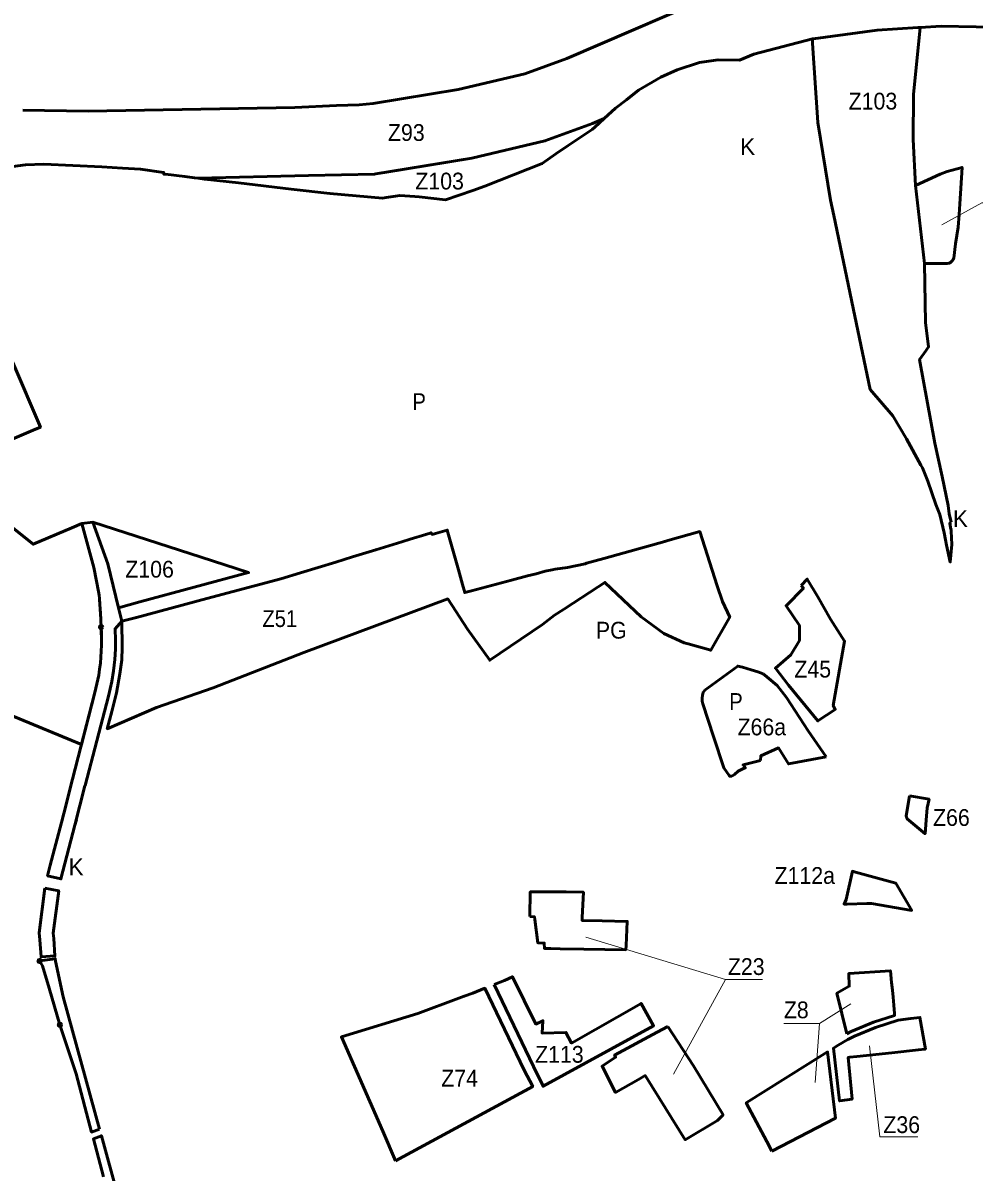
# Model space of a CAD drawing. Extents: x -650246 to -642674, y -1074280 to -1066767.
# Drawn here: x -649169 to -647810, y -1070690 to -1069047 of the extents above; entities that cross this region are included whole.
import ezdxf

# ---------------------------------------------------------------- set-up
doc = ezdxf.new("R2010")
doc.units = 0
doc.header["$LTSCALE"] = 9.6
doc.header["$PDMODE"] = 32
doc.header["$PDSIZE"] = 4.8
for name, color, linetype, lineweight in [('44', 7, 'Continuous', 53), ('45', 7, 'Continuous', 53), ('46', 7, 'Continuous', 13), ('48', 7, 'Continuous', 13), ('60', 7, 'Continuous', 35)]:
    doc.layers.add(name, color=color, linetype=linetype, lineweight=lineweight)

msp = doc.modelspace()

# ---------------------------------------------------------------- linework, layer by layer
at = {"layer": '44'}
for p, q in [((-649058.858, -1069889.759), (-649057.868, -1069910.51)), ((-649057.134, -1069932.873), (-649057.868, -1069910.51)), ((-649146.163, -1070347.543), (-649145.424, -1070357.637))]:
    msp.add_line(p, q, dxfattribs=at)
for points in [[(-648156.739, -1068996.273), (-648392.002, -1069097.554), (-648451.865, -1069119.456), (-648547.243, -1069141.81), (-648668.959, -1069161.838), (-648688.912, -1069163.603), (-648721.315, -1069164.952), (-648781.015, -1069167.44), (-649076.02, -1069172.683), (-649169.781, -1069171.432)], [(-648040.456, -1069069.483), (-648039.666, -1069069.279), (-647948.18, -1069057.276)], [(-647948.18, -1069057.276), (-648039.666, -1069069.279), (-648040.456, -1069069.483)], [(-647948.18, -1069057.276), (-647889.927, -1069053.218), (-647886.615, -1069053.052)], [(-647886.615, -1069053.052), (-647889.927, -1069053.218), (-647948.18, -1069057.276)], [(-647887.087, -1069527.229), (-647878.73, -1069515.45), (-647874.75, -1069509.84), (-647878.93, -1069475.09), (-647880.326, -1069390.832), (-647893.553, -1069279.021), (-647896.67, -1069213.573), (-647896.362, -1069149.171), (-647886.615, -1069053.052)], [(-647886.615, -1069053.052), (-647856.541, -1069051.548), (-647756.441, -1069053.207), (-647708.401, -1069056.275), (-647511.94, -1069076.703), (-647426.417, -1069084.624), (-647344.902, -1069091.02), (-647270.522, -1069094.255), (-647197.498, -1069094.255), (-647123.648, -1069091.043), (-647065.688, -1069087.73)], [(-648665.007, -1069262.694), (-648527.693, -1069239.938), (-648423.173, -1069215.44), (-648354.978, -1069190.492), (-648338.523, -1069183.389), (-648322.14, -1069168.56), (-648306.83, -1069156.57), (-648289.25, -1069142.79), (-648257.5, -1069124.41), (-648234.22, -1069113.6), (-648202.46, -1069103.3), (-648175.65, -1069099.64), (-648144.866, -1069099.987), (-648124.327, -1069091.181), (-648040.705, -1069069.547), (-648040.456, -1069069.483)], [(-648040.456, -1069069.483), (-648040.537, -1069075.531), (-648036.291, -1069139.458), (-648034.421, -1069167.61)], [(-648034.421, -1069167.61), (-648033, -1069189), (-648015, -1069300), (-648010.092, -1069322.087), (-647980.331, -1069465.915), (-647958.34, -1069570.699), (-647925.99, -1069608.57)], [(-648354.978, -1069190.492), (-648423.173, -1069215.44), (-648527.693, -1069239.938), (-648652.716, -1069260.657)], [(-648526.15, -1069286.21), (-648508.95, -1069280.01), (-648427.08, -1069247.75), (-648407.73, -1069233.88), (-648389.91, -1069221.86), (-648355.81, -1069198.88), (-648351.77, -1069195.88), (-648338.523, -1069183.389), (-648354.978, -1069190.492)], [(-649202.63, -1069254.4), (-649165.62, -1069249.43), (-649139.63, -1069248.73), (-649056.95, -1069252.55), (-649026.955, -1069254.366), (-649001.3, -1069255.92), (-648968.49, -1069260.36), (-648968.05, -1069263.06), (-648965.8, -1069262.75), (-648937.91, -1069266.51), (-648924.13, -1069268.21), (-648918.889, -1069268.875)], [(-648918.889, -1069268.875), (-648761.189, -1069265.035), (-648666.827, -1069262.738), (-648665.007, -1069262.694)], [(-648666.827, -1069262.738), (-648761.189, -1069265.035), (-648918.889, -1069268.875), (-648909.86, -1069270.02), (-648861.49, -1069275.34), (-648785.92, -1069284.2), (-648730.66, -1069290.43), (-648730.66, -1069290.43), (-648655.53, -1069297.18), (-648650.06, -1069296.39), (-648636.85, -1069294.49)], [(-648652.716, -1069260.657), (-648665.007, -1069262.694), (-648666.827, -1069262.738)], [(-648636.85, -1069294.49), (-648630.82, -1069293.63), (-648609.425, -1069295.033), (-648603.228, -1069295.53), (-648565.18, -1069299.46), (-648526.15, -1069286.21)], [(-647865.69, -1069647.32), (-647887.649, -1069528.021), (-647887.087, -1069527.229)], [(-647925.99, -1069608.57), (-647906.16, -1069641.48), (-647885.665, -1069678.788), (-647885.663, -1069678.794), (-647883.51, -1069682.71), (-647875.82, -1069701.85)], [(-647842.438, -1069760.647), (-647845.086, -1069748.753), (-647846.484, -1069736.663), (-647855.158, -1069695.232), (-647865.69, -1069647.32)], [(-647875.82, -1069701.85), (-647864.19, -1069735.12), (-647858.44, -1069749.43), (-647852.63, -1069775.7), (-647850.66, -1069785.74), (-647849.165, -1069793.367), (-647843.74, -1069817.63), (-647841.402, -1069792.351)], [(-649061.138, -1069979.243), (-649061.138, -1069979.243), (-649061.139, -1069979.254), (-649066.487, -1070004.267), (-649098.65, -1070127.795), (-649110.925, -1070177.113), (-649114.174, -1070189.816), (-649130.712, -1070250.935), (-649134.294, -1070266.095), (-649115.159, -1070270.568), (-649095.152, -1070193.731), (-649093.095, -1070186.132), (-649095.152, -1070193.731), (-649080.924, -1070137.409), (-649080.38, -1070136.996), (-649047.131, -1070009.304), (-649042.468, -1069988.477), (-649042.468, -1069988.477), (-649039.966, -1069973.035), (-649037.98, -1069956.626), (-649037.322, -1069942.129), (-649037.137, -1069928.996), (-649037.665, -1069912.977), (-649028.017, -1069902.109), (-649032.928, -1069882.782), (-649048, -1069820), (-649069.4, -1069760.67), (-649085.41, -1069762.44), (-649068, -1069825.147), (-649060.897, -1069861.994)], [(-647841.402, -1069792.351), (-647842.489, -1069773.282), (-647842.622, -1069770.956), (-647843.337, -1069769.013), (-647843.443, -1069768.293), (-647843.458, -1069768.256), (-647843.449, -1069768.252), (-647844.371, -1069761.991), (-647842.438, -1069760.647)], [(-649138.43, -1070283.6), (-649146.163, -1070347.543), (-649146.163, -1070347.543)], [(-649125.503, -1070355.837), (-649126.069, -1070348.097), (-649118.257, -1070287.455), (-649138.43, -1070283.6)], [(-649145.424, -1070357.637), (-649143.633, -1070382.123), (-649123.693, -1070380.572), (-649125.503, -1070355.837)], [(-649059.951, -1070628.223), (-649112.14, -1070439.152), (-649123.138, -1070388.16), (-649123.385, -1070384.775), (-649145.73, -1070387.91)], [(-649145.73, -1070387.91), (-649141.48, -1070394.84), (-649132.07, -1070426.81), (-649116.56, -1070479.19)], [(-649116.56, -1070479.19), (-649093.2, -1070549.1), (-649071.33, -1070632.6), (-649059.951, -1070628.223)], [(-649025.129, -1070754.377), (-649047.11, -1070674.743), (-649050.081, -1070663.981), (-649057.338, -1070637.689), (-649068.65, -1070642.23), (-649068.65, -1070642.23), (-649054.31, -1070696.44)]]:
    msp.add_lwpolyline(points, dxfattribs=at)
msp.add_lwpolyline([(-647860.52, -1069390.72), (-647848.24, -1069390.65), (-647845.25, -1069390.07), (-647843.41, -1069389.23), (-647841.81, -1069387.99), (-647840.42, -1069386.51), (-647839.4, -1069384.73), (-647838.79, -1069382.86), (-647836.2, -1069362.68), (-647832.29, -1069338.58), (-647832.29, -1069338.58), (-647831.19, -1069320.69), (-647830.23, -1069305.38), (-647826.928, -1069253.199), (-647848.17, -1069259.21), (-647858.37, -1069263.03), (-647893.553, -1069279.017), (-647880.326, -1069390.832)], close=True, dxfattribs=at)
at = {"layer": '44', "lineweight": 13}
msp.add_lwpolyline([(-647751.811, -1069303.761), (-647798.61, -1069303.761), (-647856.005, -1069335.572)], dxfattribs=at)
msp.add_lwpolyline([(-647751.811, -1069303.761), (-647798.61, -1069303.761), (-647856.005, -1069335.572)], dxfattribs=at)
at = {"layer": '44'}
for centre, radius, start, end in [((-648354.978, -1069190.492), 0.000000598, 264.13978, 298.69712), ((-649633.43, -1069918.001), 575.266, 2.81398, 5.58706), ((-649347.129, -1069931.193), 290, 350.46253, 4.08974), ((-649347.129, -1069931.193), 290, 359.66809, 4.08974)]:
    msp.add_arc(centre, radius, start, end, dxfattribs=at)
for p in [(-649145.73, -1070387.91), (-649116.56, -1070479.19)]:
    msp.add_point(p, dxfattribs=at)
at = {"layer": '45'}
for p, q in [((-649032.928, -1069882.782), (-649002.558, -1069874.585)), ((-649032.928, -1069882.782), (-649002.558, -1069874.585)), ((-649057.868, -1069910.51), (-649058.82, -1069890.548))]:
    msp.add_line(p, q, dxfattribs=at)
for points in [[(-649241.11, -1069665.9), (-649155.082, -1069629.097), (-649144.57, -1069624.6), (-649184.1, -1069532.2)], [(-649060.897, -1069861.994), (-649068, -1069825.147), (-649085.41, -1069762.44), (-649085.41, -1069762.44), (-649099.75, -1069768.575), (-649154.76, -1069792.11), (-649184.05, -1069768.45)], [(-649002.558, -1069874.585), (-648846.924, -1069832.58), (-648914.48, -1069810.75), (-649069.4, -1069760.67)], [(-649069.4, -1069760.67), (-649048, -1069820), (-649032.928, -1069882.782)], [(-649002.558, -1069874.585), (-648846.924, -1069832.58), (-648914.48, -1069810.75), (-649069.4, -1069760.67)], [(-649069.4, -1069760.67), (-649048, -1069820), (-649032.928, -1069882.782)], [(-649202.375, -1070030.469), (-649085.737, -1070078.201), (-649066.487, -1070004.267), (-649061.139, -1069979.254), (-649061.138, -1069979.243), (-649061.138, -1069979.243)], [(-648128.48, -1069971.7), (-648140.96, -1069968.01), (-648147.46, -1069966.19), (-648194.84, -1070000.49)], [(-648111.44, -1069977.32), (-648118.75, -1069974.53), (-648128.48, -1069971.7)], [(-648021.35, -1070096.14), (-648046.83, -1070058.62), (-648077.68, -1070011.06), (-648091.06, -1069994.07), (-648105.79, -1069981.56), (-648111.44, -1069977.32)], [(-648194.84, -1070000.49), (-648197.19, -1070003.94), (-648198.17, -1070008.05), (-648198.48, -1070012.3), (-648198.22, -1070016.4), (-648197.23, -1070020.37), (-648182.01, -1070067.11)], [(-648182.01, -1070067.11), (-648167.48, -1070111.75), (-648159.89, -1070122.49), (-648159.02, -1070123.71), (-648156.07, -1070123.54)], [(-648115.11, -1070101.26), (-648114.7, -1070094.68), (-648089.22, -1070083.27), (-648074.76, -1070106.17), (-648021.35, -1070096.14)], [(-648152.35, -1070121.05), (-648147.02, -1070116.35), (-648139.45, -1070112.79), (-648136.61, -1070111.97), (-648139.91, -1070107.48), (-648115.11, -1070101.26)], [(-648156.07, -1070123.54), (-648153.85, -1070122.38), (-648152.35, -1070121.05)]]:
    msp.add_lwpolyline(points, dxfattribs=at)
for points in [[(-648906.547, -1069869.711), (-649007.37, -1069896.602), (-649028.017, -1069902.109), (-649027.457, -1069939.468), (-649028.007, -1069957.455), (-649030.869, -1069977.253), (-649035.775, -1070004.354), (-649042.536, -1070031.342), (-649048.918, -1070055.852), (-648978.654, -1070025.669), (-648897.735, -1069997.25), (-648767.83, -1069946.87), (-648562.242, -1069870.301), (-648533.79, -1069913.49), (-648502.048, -1069957.969), (-648472.6, -1069937.81), (-648426.82, -1069906.88), (-648409.44, -1069893.25), (-648396.87, -1069885.43), (-648395.03, -1069884.22), (-648347.06, -1069853), (-648337.48, -1069846.531), (-648285.62, -1069895.71), (-648253.13, -1069919.7), (-648223.99, -1069932.96), (-648218.245, -1069934.595), (-648186.268, -1069943.697), (-648160.04, -1069897.73), (-648159.1, -1069896.39), (-648169.15, -1069873.81), (-648176.78, -1069851.74), (-648201.83, -1069773.86), (-648247.27, -1069786.64), (-648251.94, -1069787.95), (-648339.05, -1069812.45), (-648363.68, -1069819.31), (-648365.81, -1069819.9), (-648391.08, -1069825.45), (-648408.45, -1069827.83), (-648412.74, -1069828.72), (-648422.75, -1069830.78), (-648435.53, -1069834.44), (-648447.98, -1069837.44), (-648470.79, -1069843.51), (-648528.11, -1069858.73), (-648537.86, -1069861.22), (-648541.06, -1069849.78), (-648546.97, -1069828.68), (-648562.87, -1069771.85), (-648579.63, -1069776.66), (-648584.65, -1069778.1), (-648586.09, -1069775.75), (-648593.59, -1069778.06), (-648615.88, -1069784.93), (-648627.99, -1069788.67), (-648665.05, -1069799.99), (-648698.31, -1069810.16), (-648722.24, -1069817.54), (-648772.48, -1069832.83), (-648800.85, -1069841.52)], [(-648057.11, -1069851.12), (-648053.61, -1069854.64), (-648078.54, -1069880.01), (-648059.32, -1069908.27), (-648059.5, -1069929.52), (-648071.58, -1069950.39), (-648093.67, -1069969.42), (-648074.96, -1069993.46), (-648032.85, -1070044.73), (-648008.18, -1070028.25), (-648010.44, -1070023.66), (-648010.94, -1070022.65), (-647994.71, -1069930.53), (-648015.11, -1069898.98), (-648032.94, -1069867.46), (-648048.08, -1069841.95)], [(-648057.11, -1069851.12), (-648053.61, -1069854.64), (-648078.54, -1069880.01), (-648059.32, -1069908.27), (-648059.5, -1069929.52), (-648071.58, -1069950.39), (-648093.67, -1069969.42), (-648074.96, -1069993.46), (-648032.85, -1070044.73), (-648008.18, -1070028.25), (-648010.44, -1070023.66), (-648010.94, -1070022.65), (-647994.71, -1069930.53), (-648015.11, -1069898.98), (-648032.94, -1069867.46), (-648048.08, -1069841.95)], [(-647902.17, -1070151.64), (-647906.6, -1070180.65), (-647905.17, -1070184.5), (-647879.81, -1070206.08), (-647878.18, -1070186.33), (-647876.74, -1070168.88), (-647873.97, -1070156.58)], [(-647902.17, -1070151.64), (-647906.6, -1070180.65), (-647905.17, -1070184.5), (-647879.81, -1070206.08), (-647878.18, -1070186.33), (-647876.74, -1070168.88), (-647873.97, -1070156.58)], [(-647962.82, -1070305.9), (-647956.36, -1070305.77), (-647898.82, -1070315.51), (-647921.51, -1070276.76), (-647979.24, -1070260.71), (-647983.6, -1070259.5), (-647992.71, -1070300.01), (-647995.46, -1070306.55), (-647991.12, -1070306.46)], [(-648444.85, -1070324.47), (-648444.15, -1070289.16), (-648428.98, -1070288.92), (-648416.93, -1070288.85), (-648392.94, -1070289.25), (-648368.25, -1070289.71), (-648370.07, -1070325.94), (-648370.07, -1070329.902), (-648341.46, -1070330.48), (-648305.47, -1070331.23), (-648307.13, -1070365.57), (-648307.67, -1070371.78), (-648367.67, -1070371.16), (-648401.35, -1070370.5), (-648414.75, -1070370.24), (-648424.05, -1070370), (-648424.31, -1070362.21), (-648433.46, -1070361.94), (-648437.65, -1070328.8), (-648438.296, -1070324.598)], [(-648444.85, -1070324.47), (-648444.15, -1070289.16), (-648428.98, -1070288.92), (-648416.93, -1070288.85), (-648392.94, -1070289.25), (-648368.25, -1070289.71), (-648370.07, -1070325.94), (-648370.07, -1070329.902), (-648341.46, -1070330.48), (-648305.47, -1070331.23), (-648307.13, -1070365.57), (-648307.67, -1070371.78), (-648367.67, -1070371.16), (-648401.35, -1070370.5), (-648414.75, -1070370.24), (-648424.05, -1070370), (-648424.31, -1070362.21), (-648433.46, -1070361.94), (-648437.65, -1070328.8), (-648438.296, -1070324.598)], [(-647991.539, -1070492.016), (-647985.19, -1070488.804), (-647953.251, -1070475.276), (-647923.247, -1070465.749), (-647923.53, -1070462.75), (-647924.63, -1070451.09), (-647925.5, -1070439.63), (-647926.53, -1070429.76), (-647927.67, -1070418.74), (-647929.24, -1070401.97), (-647988.86, -1070405.95), (-647988.11, -1070423.93), (-648005.668, -1070434.145)], [(-648495.666, -1070421.476), (-648439.409, -1070538.729), (-648425.835, -1070567.021), (-648267.801, -1070480.55), (-648285.75, -1070448.49), (-648385.085, -1070505.351), (-648393.14, -1070490.07), (-648427.41, -1070491.08), (-648426.05, -1070473.34), (-648436.22, -1070478.01), (-648469.77, -1070410.47), (-648481.18, -1070415.62)], [(-648495.666, -1070421.476), (-648439.409, -1070538.729), (-648425.835, -1070567.021), (-648267.801, -1070480.55), (-648285.75, -1070448.49), (-648385.085, -1070505.351), (-648393.14, -1070490.07), (-648427.41, -1070491.08), (-648426.05, -1070473.34), (-648436.22, -1070478.01), (-648469.77, -1070410.47), (-648481.18, -1070415.62)], [(-648636.757, -1070673.431), (-648550.72, -1070626.869), (-648440.531, -1070567.236), (-648452.97, -1070544.21), (-648509.227, -1070426.957), (-648526.28, -1070433.85), (-648538.611, -1070438.388), (-648546.377, -1070441.246), (-648604.92, -1070462.79), (-648714.161, -1070496.376), (-648655.178, -1070631.294)], [(-647950.48, -1070482.79), (-647980.4, -1070495.463), (-647990.295, -1070500.352), (-648003.85, -1070508.218), (-648010.831, -1070512.588), (-648002, -1070588), (-647984.03, -1070585.46), (-647989.5, -1070525.73), (-647987.436, -1070525.508), (-647977.41, -1070524.43), (-647927.14, -1070519), (-647889.27, -1070514.92), (-647879.89, -1070513.91), (-647879.16, -1070513.83), (-647887.08, -1070468.54), (-647899.87, -1070470.04), (-647917.98, -1070472.47)], [(-648247.67, -1070481.57), (-648262.69, -1070489.67), (-648323.59, -1070522.48), (-648322.18, -1070525.44), (-648341.41, -1070538.42), (-648322.16, -1070575.76), (-648289.22, -1070557.15), (-648279.736, -1070551.783), (-648278.89, -1070553.14), (-648222.58, -1070643.48), (-648176.54, -1070616.09), (-648168.575, -1070607.847), (-648211, -1070538)], [(-648247.67, -1070481.57), (-648262.69, -1070489.67), (-648323.59, -1070522.48), (-648322.18, -1070525.44), (-648341.41, -1070538.42), (-648322.16, -1070575.76), (-648289.22, -1070557.15), (-648279.736, -1070551.783), (-648278.89, -1070553.14), (-648222.58, -1070643.48), (-648176.54, -1070616.09), (-648168.575, -1070607.847), (-648211, -1070538)], [(-648098.637, -1070659.682), (-648007.838, -1070612.851), (-648019, -1070518), (-648135.47, -1070590.61), (-648105.98, -1070645.91)]]:
    msp.add_lwpolyline(points, close=True, dxfattribs=at)
for centre, radius, start, end in [((-649649.71, -1069919.176), 591.583, 2.77379, 5.54687), ((-649347.129, -1069931.193), 290, 350.46253, 4.08974)]:
    msp.add_arc(centre, radius, start, end, dxfattribs=at)
msp.add_point((-649057.868, -1069910.51), dxfattribs=at)
at = {"layer": '46'}
for p, q in [((-648165.109, -1070414.543), (-648239.52, -1070549.62)), ((-648165.109, -1070414.543), (-648239.52, -1070549.62)), ((-648030.462, -1070477.049), (-648036.992, -1070561.483)), ((-647944.293, -1070639.492), (-647959.279, -1070509.201)), ((-647890.215, -1070639.492), (-647944.293, -1070639.492)), ((-647890.215, -1070639.492), (-647904.43, -1070639.492))]:
    msp.add_line(p, q, dxfattribs=at)
for points in [[(-648112.329, -1070414.543), (-648165.109, -1070414.543), (-648364.98, -1070353.932)], [(-648112.329, -1070414.543), (-648165.109, -1070414.543), (-648364.98, -1070353.932)], [(-648081.63, -1070477.049), (-648030.462, -1070477.049), (-647985.902, -1070448.995)]]:
    msp.add_lwpolyline(points, dxfattribs=at)

# ---------------------------------------------------------------- texts
at = {"layer": '44', "width": 0.95}
for s, p in [('Z103', (-647989.032, -1069170.515)), ('Z103', (-647989.032, -1069170.515)), ('Z93', (-648647.673, -1069215.426)), ('Z93', (-648647.673, -1069215.426)), ('Z103', (-648608.542, -1069284.81)), ('Z103', (-648608.542, -1069284.81))]:
    msp.add_text(s, height=24, dxfattribs=at).set_placement(p)
at = {"layer": '46'}
for s, width, p in [('Z106', 0.95, (-649023.189, -1069839.754)), ('Z106', 0.95, (-649023.189, -1069839.754)), ('Z51', 0.9, (-648827.214, -1069910.388)), ('Z45', 0.95, (-648066.663, -1069982.614)), ('Z45', 0.95, (-648066.663, -1069982.614)), ('Z66a', 0.95, (-648147.889, -1070065.308)), ('Z66', 0.95, (-647868.376, -1070194.801)), ('Z112a', 0.95, (-648094.972, -1070277.658)), ('Z23', 0.95, (-648161.708, -1070407.912)), ('Z23', 0.95, (-648161.708, -1070407.912)), ('Z8', 0.95, (-648081.661, -1070469.822)), ('Z113', 0.95, (-648437.324, -1070533.384)), ('Z113', 0.95, (-648437.324, -1070533.384)), ('Z74', 0.95, (-648571.565, -1070567.472)), ('Z36', 0.95, (-647939.415, -1070633.92)), ('Z36', 0.95, (-647939.415, -1070633.92))]:
    msp.add_text(s, height=24, dxfattribs=dict(at, width=width)).set_placement(p)
at = {"layer": '48'}
for p in [(-648144.004, -1069235.577), (-648144.004, -1069235.577), (-647839.874, -1069767.492), (-649104.211, -1070265.34)]:
    msp.add_text('K', height=24, dxfattribs=at).set_placement(p)
at = {"layer": '60'}
for s, width, p in [('P', 0.9, (-648612.658, -1069600.244)), ('PG', 0.95, (-648350.408, -1069926.995)), ('P', 0.9, (-648159.699, -1070028.97))]:
    msp.add_text(s, height=24, dxfattribs=dict(at, width=width)).set_placement(p)

doc.saveas('drawing.dxf')
